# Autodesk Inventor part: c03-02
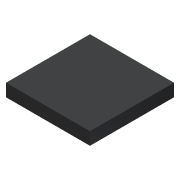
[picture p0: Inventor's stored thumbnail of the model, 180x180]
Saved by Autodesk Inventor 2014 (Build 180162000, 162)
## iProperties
Created: 2011-11
Part Number: c03-02
Material: Generic
Document SubType Name: Modeling
Designer: Thom Tremblay
Density: 1 g/cm^3
Appearance: Generic
Author: Thom Tremblay
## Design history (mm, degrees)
sketch "Sketch1"
  geometry: L1 (50, 50)-(50, -50); L2 (50, -50)-(-50, -50); L3 (-50, -50)-(-50, 50); L4 (-50, 50)-(50, 50); 2 further points
  constraints: 8 end point, 1 coincident, 1 horizontal, 9 other
  dimensions: "d2" = 100 distance between parallel lines of L3 L1
extrude "Extrusion1" new body sketch "Sketch1" distance "d3" = 15; taper "d4" = 0 deg
body "Solid1"
